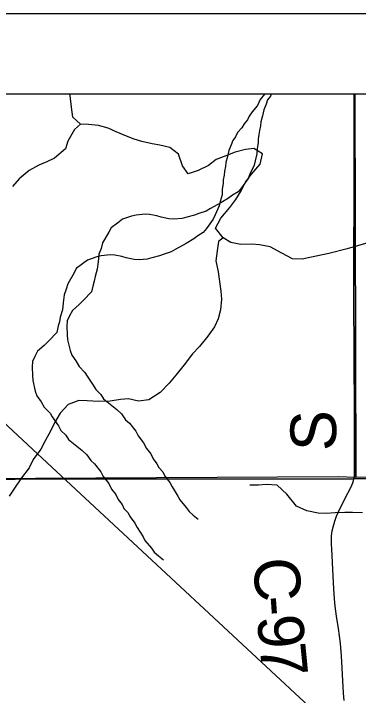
# Model space of a CAD drawing. Extents: x -21.1 to 50.3, y -4.9 to 22.1.
# Drawn here: x 5.461 to 5.889, y 20.154 to 21 of the extents above; entities that cross this region are included whole.
import ezdxf

# ---------------------------------------------------------------- set-up
doc = ezdxf.new("R2010")
doc.units = 0
for name, color, linetype in [('GM_X_Corporation', 7, 'Continuous'), ('GM_X_County', 7, 'Continuous'), ('GM_X_County_Road', 7, 'Continuous'), ('GM_X_County_Road_Text', 7, 'Continuous'), ('GM_X_Minor_River', 7, 'Continuous'), ('GM_X_Rail_Line', 7, 'Continuous'), ('GM_X_Rail_Line_Text', 7, 'Continuous'), ('SH_Cut_Line', 7, 'Continuous'), ('SH_Data', 7, 'Continuous')]:
    doc.layers.add(name, color=color, linetype=linetype)

msp = doc.modelspace()

# ---------------------------------------------------------------- linework, layer by layer
at = {"layer": 'GM_X_Corporation'}
for points in [[(5.88454, 20.9), (4.88034, 20.9), (4.88576, 20.41997), (5.86397, 20.4254), (5.88596, 20.42484)], [(6.88768, 20.9), (5.88454, 20.9), (5.88596, 20.42484), (6.89298, 20.43015)]]:
    msp.add_lwpolyline(points, close=True, dxfattribs=at)
at = {"layer": 'GM_X_County'}
msp.add_lwpolyline([(8.9, 14.74638), (8.9, 20.9), (2.1, 20.9), (2.1, 14.1), (8.89319, 14.1)], dxfattribs=at)
at = {"layer": 'GM_X_County_Road'}
for points in [[(5.88352, 20.42225), (5.88378, 20.42323), (5.88418, 20.42617), (5.88431, 20.43227), (5.88416, 20.44467), (5.88408, 20.46646), (5.88408, 20.48201), (5.8841, 20.50685), (5.88412, 20.51927), (5.88393, 20.55963), (5.88383, 20.57205), (5.88367, 20.59691), (5.88357, 20.62798), (5.88355, 20.6435), (5.88339, 20.66832), (5.88331, 20.68697), (5.88339, 20.70252), (5.88355, 20.72114), (5.88364, 20.74904), (5.88366, 20.80185), (5.88374, 20.83288), (5.88385, 20.85458), (5.88378, 20.87011), (5.88395, 20.9)], [(5.87136, 20.14751), (5.87057, 20.15638), (5.86902, 20.18744), (5.86805, 20.20292), (5.86672, 20.21833), (5.86559, 20.22753), (5.86419, 20.23674), (5.86186, 20.2521), (5.86039, 20.26444), (5.85952, 20.27373), (5.85856, 20.28613), (5.85768, 20.30161), (5.85612, 20.33552), (5.85577, 20.34152), (5.85556, 20.34614), (5.85571, 20.35194), (5.85663, 20.358), (5.85794, 20.36414), (5.85961, 20.37018), (5.86166, 20.37612), (5.86427, 20.38185), (5.8727, 20.39876), (5.87957, 20.41194), (5.88201, 20.41759), (5.88305, 20.42041), (5.88352, 20.42225)]]:
    msp.add_lwpolyline(points, dxfattribs=at)
at = {"layer": 'GM_X_Minor_River'}
for points in [[(5.80723, 20.69553), (5.79396, 20.70273), (5.77956, 20.7107), (5.76629, 20.71297), (5.75682, 20.71373), (5.74317, 20.71335), (5.73066, 20.716), (5.72119, 20.72169), (5.71172, 20.73382), (5.71817, 20.74596), (5.72917, 20.75923), (5.73675, 20.7691), (5.74358, 20.78009), (5.7489, 20.79071), (5.75611, 20.80095), (5.76711, 20.81309), (5.76977, 20.82598), (5.75915, 20.83281), (5.74892, 20.83129), (5.73603, 20.82788), (5.72427, 20.82371), (5.71252, 20.81877), (5.70304, 20.81157), (5.69015, 20.8055), (5.67763, 20.80132), (5.67044, 20.81119), (5.66552, 20.82559), (5.65491, 20.83394), (5.6424, 20.83659), (5.63292, 20.83848), (5.62003, 20.84114), (5.61056, 20.84417), (5.60108, 20.84796), (5.5882, 20.85327), (5.57834, 20.85782), (5.56621, 20.86123), (5.5537, 20.86237), (5.54385, 20.86275), (5.53438, 20.87147), (5.53287, 20.88398), (5.53098, 20.8984), (5.53022, 20.9)], [(5.7725, 20.9), (5.76698, 20.89332), (5.7636, 20.88608), (5.75717, 20.87807), (5.75339, 20.87273), (5.75113, 20.86816), (5.74698, 20.8632), (5.74434, 20.85824), (5.73904, 20.85251), (5.73641, 20.84718), (5.73301, 20.8426), (5.73113, 20.83728), (5.72813, 20.83004), (5.72664, 20.82281), (5.7244, 20.8152), (5.72405, 20.81026), (5.72294, 20.80456), (5.72221, 20.79961), (5.7211, 20.79353), (5.72113, 20.78897), (5.72002, 20.78213), (5.71968, 20.77529), (5.71744, 20.76692), (5.71633, 20.76159), (5.71106, 20.75017), (5.70881, 20.74484), (5.7005, 20.73339), (5.69634, 20.72843), (5.68951, 20.72421), (5.68459, 20.72039), (5.6751, 20.71464), (5.6622, 20.70773), (5.65651, 20.70428), (5.64777, 20.70157), (5.64207, 20.69925), (5.63256, 20.69692), (5.62686, 20.69537), (5.61659, 20.69456)], [(5.78083, 20.9), (5.77969, 20.8977), (5.77629, 20.89312), (5.77442, 20.88779), (5.77142, 20.88056), (5.76993, 20.87333), (5.76769, 20.86572), (5.76734, 20.86078), (5.76623, 20.85507), (5.7655, 20.85013), (5.76439, 20.84405), (5.76441, 20.83949), (5.76331, 20.83264), (5.76297, 20.8258), (5.76073, 20.81743), (5.75962, 20.81211), (5.75435, 20.80068), (5.7521, 20.79535), (5.74379, 20.78391), (5.73963, 20.77895), (5.7328, 20.77473), (5.72787, 20.7709), (5.71839, 20.76515), (5.70548, 20.75824), (5.69979, 20.75479), (5.69105, 20.75208), (5.68536, 20.74977), (5.67585, 20.74744), (5.67015, 20.74589), (5.65988, 20.74507)], [(5.54385, 20.86275), (5.53664, 20.8563), (5.52829, 20.84151), (5.52526, 20.83203), (5.5116, 20.82065), (5.50212, 20.8161), (5.49226, 20.81192), (5.48013, 20.80547), (5.46761, 20.79486), (5.45927, 20.78537)], [(5.65988, 20.74507), (5.65379, 20.74542), (5.64388, 20.74726), (5.63854, 20.74913), (5.62978, 20.7506), (5.62407, 20.75095), (5.61303, 20.74975), (5.60733, 20.74858), (5.59593, 20.74472), (5.58987, 20.74013), (5.58191, 20.734), (5.57927, 20.72867), (5.57135, 20.71533), (5.56949, 20.70848), (5.56686, 20.70163), (5.56578, 20.69174), (5.56468, 20.683), (5.56207, 20.67387), (5.56096, 20.66778), (5.55947, 20.66322), (5.55761, 20.65485), (5.54777, 20.64454), (5.54209, 20.63881), (5.53376, 20.63154), (5.53037, 20.62506), (5.52736, 20.61859), (5.52701, 20.61213), (5.52745, 20.60149), (5.52787, 20.59504), (5.53099, 20.58176), (5.53293, 20.57607), (5.5383, 20.56888), (5.54214, 20.56207), (5.54941, 20.55451), (5.55211, 20.54996), (5.55978, 20.53899), (5.56286, 20.53331), (5.56898, 20.52726), (5.57244, 20.52196), (5.58888, 20.50876), (5.595, 20.50309), (5.59999, 20.49591), (5.60458, 20.49175), (5.61263, 20.48192), (5.61533, 20.47585), (5.62223, 20.46716), (5.62569, 20.46034), (5.63106, 20.45353), (5.63414, 20.44747), (5.63874, 20.44141), (5.64105, 20.43649), (5.64603, 20.4312), (5.64872, 20.42589), (5.65486, 20.41795), (5.65755, 20.41265), (5.66485, 20.40129), (5.66716, 20.39674), (5.67521, 20.38691), (5.67866, 20.38199), (5.68402, 20.37746), (5.69014, 20.37256)], [(5.72119, 20.72169), (5.7155, 20.71714), (5.7136, 20.70576), (5.71207, 20.69324), (5.71472, 20.67959), (5.71812, 20.6557), (5.71887, 20.64546), (5.71773, 20.63219), (5.71507, 20.62119), (5.71013, 20.61133), (5.70217, 20.59957), (5.69154, 20.58705), (5.6832, 20.57757), (5.67258, 20.56429), (5.66233, 20.5514), (5.65399, 20.54116), (5.64299, 20.52978), (5.62896, 20.52068), (5.61607, 20.51916), (5.60356, 20.52181), (5.5937, 20.52105), (5.58081, 20.51915), (5.56641, 20.51839), (5.55238, 20.51953), (5.54177, 20.51991), (5.5285, 20.51497), (5.51863, 20.50398), (5.51143, 20.49222), (5.50687, 20.48274), (5.50004, 20.46984), (5.49473, 20.45922), (5.48524, 20.44671), (5.48031, 20.43646), (5.47082, 20.42395), (5.46172, 20.41105), (5.45527, 20.40119)], [(5.90087, 20.71564), (5.87509, 20.70805), (5.85234, 20.70236), (5.83869, 20.69933), (5.82883, 20.69743), (5.81936, 20.69515), (5.80723, 20.69553)], [(5.61659, 20.69456), (5.6105, 20.6949), (5.60059, 20.69675), (5.59525, 20.69862), (5.58649, 20.70009), (5.58078, 20.70043), (5.56974, 20.69924), (5.56404, 20.69806), (5.55264, 20.6942), (5.54658, 20.68961), (5.53862, 20.68349), (5.53598, 20.67815), (5.52806, 20.66481), (5.5262, 20.65797), (5.52357, 20.65111), (5.52249, 20.64123), (5.52139, 20.63248), (5.51878, 20.62335), (5.51767, 20.61727), (5.51618, 20.6127), (5.51432, 20.60433), (5.50448, 20.59402), (5.4988, 20.58829), (5.49047, 20.58103), (5.48708, 20.57455), (5.48407, 20.56807), (5.48373, 20.56161), (5.48417, 20.55098), (5.48458, 20.54452), (5.4877, 20.53124), (5.48964, 20.52556), (5.49501, 20.51837), (5.49885, 20.51155), (5.50613, 20.50399), (5.50882, 20.49945), (5.51649, 20.48847), (5.51957, 20.48279), (5.52569, 20.47675), (5.52915, 20.47145), (5.54559, 20.45824), (5.55171, 20.45258), (5.5567, 20.44539), (5.56129, 20.44123), (5.56934, 20.4314), (5.57204, 20.42534), (5.57894, 20.41664), (5.5824, 20.40982), (5.58777, 20.40301), (5.59085, 20.39695), (5.59545, 20.3909), (5.59777, 20.38597), (5.60274, 20.38068), (5.60544, 20.37538), (5.61157, 20.36743), (5.61427, 20.36213), (5.62156, 20.35077), (5.62387, 20.34623), (5.63192, 20.3364), (5.63538, 20.33147), (5.64073, 20.32695), (5.64685, 20.32204)], [(5.89425, 20.38038), (5.88174, 20.38076), (5.87226, 20.38076), (5.86013, 20.38037), (5.84913, 20.37962), (5.83928, 20.37999), (5.82487, 20.38303), (5.81237, 20.38871), (5.80024, 20.4035), (5.78812, 20.41488), (5.77447, 20.41564), (5.765, 20.41488), (5.75438, 20.41487)]]:
    msp.add_lwpolyline(points, dxfattribs=at)
at = {"layer": 'GM_X_Rail_Line'}
msp.add_lwpolyline([(8.7124, 19.43847), (8.63211, 19.49474), (8.55687, 19.56391), (8.48461, 19.63108), (8.43513, 19.68018), (7.76772, 19.77988), (6.96001, 19.8904), (6.09457, 20.00326), (6.00009, 20.01878), (5.95244, 20.04098), (5.91673, 20.06211), (5.889, 20.08519), (5.85137, 20.11828), (5.49069, 20.45383), (5.17674, 20.74571), (5.04158, 20.86318), (4.98505, 20.89838), (4.98159, 20.9)], dxfattribs=at)
at = {"layer": 'GM_X_Rail_Line_Text'}
for points in [[(8.9, 20.9), (2.80139, 20.9)], [(3.30961, 20.41539), (3.87473, 20.42102), (4.62093, 20.42151), (5.88332, 20.42279), (6.48301, 20.42563)], [(6.48301, 20.42563), (5.88332, 20.42279), (4.62093, 20.42151), (3.87473, 20.42102), (3.30961, 20.41539)]]:
    msp.add_lwpolyline(points, dxfattribs=at)
at = {"layer": 'SH_Cut_Line'}
msp.add_lwpolyline([(8.9, 16.40522), (8.9, 20.9), (2.1, 20.9)], dxfattribs=at)
at = {"layer": 'SH_Data'}
msp.add_line((2, 21), (9, 21), dxfattribs=at)

# ---------------------------------------------------------------- texts
at = {"layer": 'GM_X_County_Road_Text'}
for s, rotation, p in [('S', 90, (5.86147, 20.45709)), ('C', 273.17475, (5.75858, 20.32358)), ('-', 274.23371, (5.76124, 20.27584)), ('9', 275.01794, (5.76303, 20.25173)), ('7', 275.66246, (5.76615, 20.21617))]:
    msp.add_text(s, height=0.05682, rotation=rotation, dxfattribs=at).set_placement(p)

doc.saveas('drawing.dxf')
